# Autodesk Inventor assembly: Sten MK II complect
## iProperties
Created: 2006-04
Part Number: Sten MK II complect
Checked By: Проверил
Description: Наименование
Document SubType Name: Assembly
Mfg Approved By: Утвердил
Designer: Калинин
Engineer: Технолог
Manufacturer: Standard
Standards Organization: Custom
Author: Калинин
